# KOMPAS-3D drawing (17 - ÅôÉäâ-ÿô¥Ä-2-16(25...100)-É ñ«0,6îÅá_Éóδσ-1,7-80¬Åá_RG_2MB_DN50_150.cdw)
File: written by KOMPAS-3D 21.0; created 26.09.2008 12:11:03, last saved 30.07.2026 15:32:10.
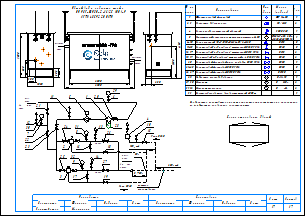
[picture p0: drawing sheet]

Sheets 1-2: A3, landscape

Document properties: Наименование: Макро:21; Автор: RaskoAdmin; Форматы листов документа: 2xA3; Полное имя файла: \\ur38nt01\Departments\КТО\КБ ПУРДГ\Заявки\Прайс-лист на типовые шкафы ГРПШ\ПУРДГ_стандарт_30_04_2026\ПУРДГ с RG_2MB\ПУРДГ-ШУЭО-2-16(25...100)-Р до0,6МПа_Рвых-1,7-80кПа_RG_2MB_DN50_150.cdw

Title block, sheet 1: Наименование: Пункт учета газа / ПУГ-Ш-400-Р / ЛГТИ.485922.001ТУ; designation: ЛГТИ.03.4411141; sheet number: 1; Количество листов документа: 2; organisation: ООО "ЭЛЬСТЕР Газэлектроника"; Форматы листов документа: A3; stored path: C:\Рабочие документы\Компас\ПУГ\Схема.cdw; Разработал: Устинов; Проверил: Кошкин; Утвердил: Кошкин
Title block, sheet 2: sheet number: 2; stored path: D:\Рабочие документы\Заявки\ПУРДГ\ПУРДГ-ШУЭО-2-100-Р 4411220.cdw; designation, second copy: ЛГТИ.03.4411141-

Views: Вид 1, Вид 2
Referenced files: wcvoit.frw
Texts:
  Normal
  DN150
  Выход газа
  DN50
  Вход газа
  logo-rasko-ge.png
  DN 1
  местное
  сопротивление
  Римп DN20
  Выход
  газа
  Р=     кПа
  Вход
  Р=       МПа
  PDI
  Общий вид и габариты шкафа
  ПУРДГ-ШУЭО-2-16(25...100)-Р
  № на
  схеме
  Усл.
  обозн.
  Марка
  (модель)
  Кол.
  Фильтр газовый фланцевый
  ФГ 16-50
  Регулятор давления газа
  RG/2MB
  Клапан предохранительный сбросной
  КПС DN20
  Измерительный комплекс с ротационным счетчиком Ду50
  СГ-ЭК-Р-(0,2...2,0)-
  Кран кнопочный VE-РАСКО-НЗ-1,6-G1/2-М20
  DN15
  Кран шаровой "под приварку" штуцерный DN20 PN16
  DN20
  Кран шаровой "под приварку" штуцерный DN15 PN16
  Кран шаровой "под приварку" штуцерный п/п DN20 PN16
  Кран шаровой фланцевый с мех. приводом DN50 PN16
  Кран шаровой фланцевый DN50 PN16
  Кран шаровой фланцевый DN150 PN16
  Индикатор перепада давления
  Манометр
  Манометр-напоромер
  Электрообогреватель взрывозащищенный 400Вт
  Delta 15
  0...     МПа
  0...     кПа
  Схема открывания дверей
  Предприятие изготовитель может заменять комплектующие на аналогичные,
  не ухудшающие заявленных характеристик.
  Должность
  Конструктор
  Фамилия
  Подпись
  Дата
  Согласовано
  Максимкин
  Лист
  Листов
  POLYLINE_STYLE_0.18_RGB_0_0_0
  POLYLINE_STYLE_0.50_RGB_0_0_0
  POLYLINE_STYLE_0.34_RGB_0_0_0
  PHANTOM_RGB_0_0_0_SC_1_THICK_0.18
  K5LT_THIN_RGB_0_0_0_THICK_0.18
  K5LT32769_RGB_0_0_0_THICK_0.18
  K5LT12_RGB_0_0_0_SC_1_THICK_0.18
  K5LT_DASHED_RGB_0_0_0_SC_1_THICK_0.18
  ACISOTGL_RGB_0_0_0_SC_0.8_THICK_0.25
  CONTINUOUS_RGB_0_127_31_THICK_0.3
  CONTINUOUS_RGB_0_0_255_THICK_0.35
  CONTINUOUS_RGB_255_0_0_THICK_0.35
  POLYLINE_STYLE_0.25_RGB_0_0_0
  CONTINUOUS_RGB_0_0_0_THICK_0.5
  POLYLINE_STYLE_0.35_RGB_0_0_255
  CONTINUOUS_RGB_0_0_0_THICK_0.4
  CONTINUOUS_RGB_0_0_0_THICK_0.35
  НЕВИДИМАЯ_RGB_0_0_0_SC_0.3_THICK_0.25
  СONTINUOUS_RGB_0_0_0_THICK_0.25
  ОСЕВАЯ2_RGB_248_153_30_SC_0.3_THICK_0.25
  Без оформления
Dimensions and other numbers on the sheet: 1; 1500; 250; 300; 1050; 550; 305; 2500; 4130; 2000; 2800; 5,,,7DN 1; 7; 30; 12; 21; 22; 23; 11; 5; 20; 6; 29; 24; 31; 8; 2; 16; 13; 26; 18; 4; 10; 15; 25; 32; 9; 3; 17; 14; 27; 19; 28; 2, 3; 6-10; 11-15; 16, 17; 18, 19; 21-25; 26, 27; 29, 30; 31, 32; 33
